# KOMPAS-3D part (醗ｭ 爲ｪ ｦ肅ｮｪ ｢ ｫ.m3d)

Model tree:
1. Эскиз:1
2. Операция выдавливания:1
     Расстояние 1 = 6
3. Эскиз:2
4. Операция выдавливания:2
     Расстояние 1 = 1
5. Эскиз:3
6. Операция выдавливания:3
     Расстояние 1 = 9.5
7. Эскиз:4
8. Операция выдавливания:4
     Расстояние 1 = 4
9. Фаска:2
     Угол = 45; Длина 1 = 1.4; Длина 2 = 1.4
10. Фаска:3
     Угол = 45; Длина 1 = 0.5; Длина 2 = 0.5
11. Фаска:4
     Угол = 45; Длина 1 = 0.5; Длина 2 = 0.5
